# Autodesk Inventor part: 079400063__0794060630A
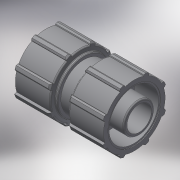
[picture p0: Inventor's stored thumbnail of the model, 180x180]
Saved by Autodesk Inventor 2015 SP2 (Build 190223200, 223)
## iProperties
Created: 2017-04
Part Number: 079400063__0794060630A
Material: Generic
Description: PLASSON MODULAR ADAPTOR 63
Document SubType Name: Modeling
Designer: KIM
Mass: 549.094 g
Surface Area: 1072.3 cm^2
Volume: 549.094 cm^3
Density: 1 g/cm^3
Appearance: Default
Author: KIM
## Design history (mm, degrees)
derived "07940.ipt"
feature "Solid1::07940.ipt"
tag "TaggingFeature1"
body "Solid1"
other parameters: "d7" = 113, "d8" = 90.4, "d9" = 63, "d15" = 84.75, "d17" = 47.6, "d43" = 100 deg, "d46" = 105.09, "d47" = 35 deg, "d48" = 17.5 deg, "d50" = 0, "d52" = 360 deg, "d54" = 2.26, "d57" = 2.26, "d68" = 42.84, "d69" = 0.5, "d70" = 4.284, "d71" = 5, "d72" = 50.4, "d73" = 59.5, "d74" = 53.55, "d75" = 79.1, "d76" = 1.13, "d77" = 2.26, "d79" = 360 deg, "d81" = 2.26, "d82" = 23.8, "d_" = 63, "E_" = 113, "H_" = 119
